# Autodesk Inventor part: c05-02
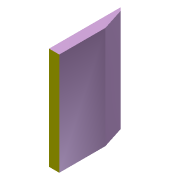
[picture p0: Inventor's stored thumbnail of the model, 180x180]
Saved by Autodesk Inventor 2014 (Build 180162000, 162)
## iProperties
Created: 2010-11
Part Number: c05-02
Material: Generic
Document SubType Name: Modeling
Designer: Thom Tremblay
Density: 1 g/cm^3
Appearance: Satin - Lavender
Author: Thom Tremblay
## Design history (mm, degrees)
sketch "Sketch1"
  geometry: L1 (0, 0)-(10, 0); L2 (10, 0)-(10, 70); L3 (10, 70)-(0, 70); L4 (0, 70)-(0, 0); L5 (3, 67)-(10, 45); L6 (0, 70)-(3, 67); 1 further point
  constraints: 12 end point, 2 parallel, 2 point on line, 1 horizontal, 1 perpendicular
  dimensions: "d0" = 10 distance of L3.end L2.end; "d1" = 70 distance of L2.end L1.end; "d3" = 25 vertical distance of point (2.045, 70) L5.end; "d6" = 45 deg angle of L4 L6; "d7" = 3 distance from line of L4 L5.start
extrude "Extrusion1" new body sketch "Sketch1" stored distance "d4" = 100; taper "d5" = 0 deg
body "Solid1"
